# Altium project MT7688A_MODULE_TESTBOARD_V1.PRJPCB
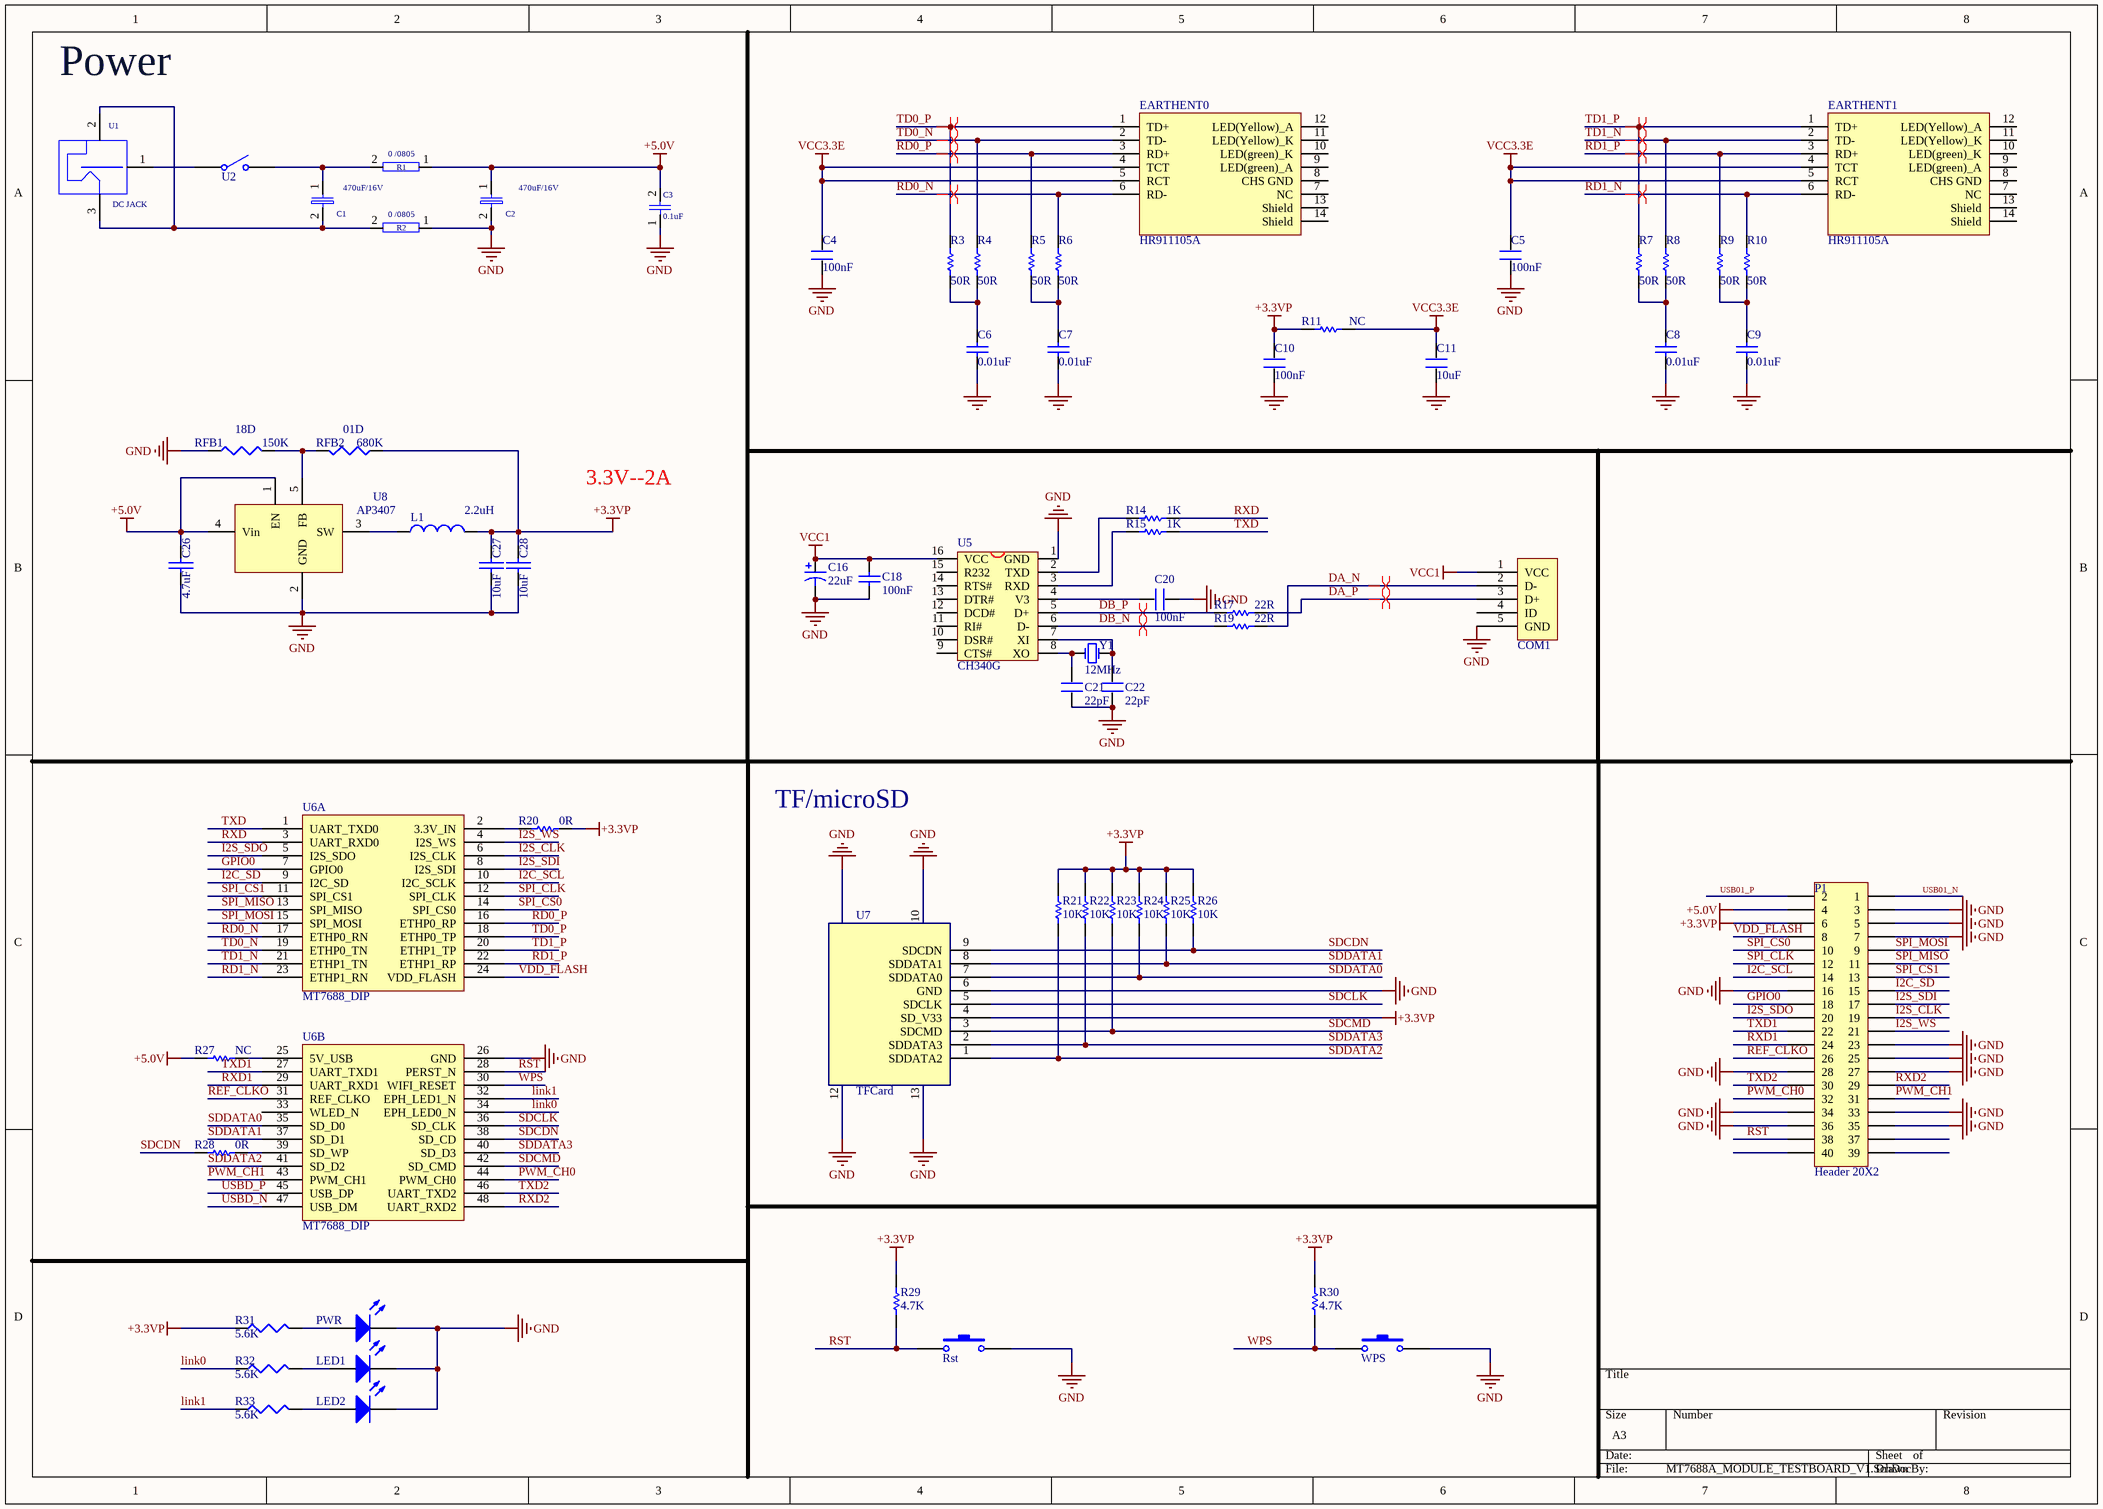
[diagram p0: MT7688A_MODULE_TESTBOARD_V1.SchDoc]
3 sheets, 120 parts. Net scope: global (net labels, ports and power ports of the same name join across sheets).
Sheets:
  MT7688A_MODULE_TESTBOARD_V1.SchDoc
  wm8960.SchDoc
  GL850G.SchDoc

## Sheet MT7688A_MODULE_TESTBOARD_V1.SchDoc
size A3

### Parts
C1  value 470uF/16V  [DL3 SMT470uF]  (hidden comment: E_CAP/3580)
C2  value 470uF/16V  [DL3 SMT470uF]  (hidden comment: E_CAP/3580)
C3  value 0.1uF  [RLC 0402 M35]  (hidden comment: CAP/0402)
C4  100nF  [RLC 0402 M35]
C5  100nF  [RLC 0402 M35]
C6  value 0.01uF  [RLC 0402 M35]  (hidden comment: Cap Semi)
C7  value 0.01uF  [RLC 0402 M35]  (hidden comment: Cap Semi)
C8  value 0.01uF  [RLC 0402 M35]  (hidden comment: Cap Semi)
C9  value 0.01uF  [RLC 0402 M35]  (hidden comment: Cap Semi)
C10  100nF  [RLC 0402 M35]
C11  10uF  [RLC 0402 M35]
C16  22uF  [C1206L]
C18  value 100nF  [RLC 0402 M35]  (hidden comment: Cap Semi)
C20  100nF  [RLC 0402 M35]
C21  22pF  [RLC 0402 M35]
C22  22pF  [RLC 0402 M35]
C26  4.7uF  [RLC 0402 M35]
C27  10uF  [RLC 0402 M35]
C28  10uF  [RLC 0402 M35]
COM1  USB mini-b  [USB mini-B]  (value not drawn)
EARTHENT0  HR911105A  [HR911105A]
EARTHENT1  HR911105A  [HR911105A]
L1  2.2uH  [L5.5x5.5]
LED1  leds_0603  [leds_0603]  (value not drawn)
LED2  leds_0603  [leds_0603]  (value not drawn)
P1  Header 20X2  [HDR2X20]
PWR  leds_0603  [leds_0603]  (value not drawn)
R1  value 0 /0805  [0805]  (hidden comment: RES/0805)
R2  value 0 /0805  [0805]  (hidden comment: RES/0805)
R3  value 50R  [RLC 0402 M35]  (hidden comment: Res Semi)
R4  value 50R  [RLC 0402 M35]  (hidden comment: Res Semi)
R5  value 50R  [RLC 0402 M35]  (hidden comment: Res Semi)
R6  value 50R  [RLC 0402 M35]  (hidden comment: Res Semi)
R7  value 50R  [RLC 0402 M35]  (hidden comment: Res Semi)
R8  value 50R  [RLC 0402 M35]  (hidden comment: Res Semi)
R9  value 50R  [RLC 0402 M35]  (hidden comment: Res Semi)
R10  value 50R  [RLC 0402 M35]  (hidden comment: Res Semi)
R11  value NC  [R0603]  (hidden comment: Res Semi)
R14  value 1K  [RLC 0402 M35]  (hidden comment: Res Semi)
R15  value 1K  [RLC 0402 M35]  (hidden comment: Res Semi)
R17  value 22R  [RLC 0402 M35]  (hidden comment: Res Semi)
R19  value 22R  [RLC 0402 M35]  (hidden comment: Res Semi)
R20  value 0R  [RLC 0402 M35]  (hidden comment: Res Semi)
R21  value 10K  [RLC 0402 M35]  (hidden comment: Res Semi)
R22  value 10K  [RLC 0402 M35]  (hidden comment: Res Semi)
R23  value 10K  [RLC 0402 M35]  (hidden comment: Res Semi)
R24  value 10K  [RLC 0402 M35]  (hidden comment: Res Semi)
R25  value 10K  [RLC 0402 M35]  (hidden comment: Res Semi)
R26  value 10K  [RLC 0402 M35]  (hidden comment: Res Semi)
R27  value NC  [RLC 0402 M35]  (hidden comment: Res Semi)
R28  value 0R  [RLC 0402 M35]  (hidden comment: Res Semi)
R29  value 4.7K  [RLC 0402 M35]  (hidden comment: Res Semi)
R30  value 4.7K  [RLC 0402 M35]  (hidden comment: Res Semi)
R31  value 5.6K  [RLC 0402 M35]  (hidden comment: Res3)
R32  value 5.6K  [RLC 0402 M35]  (hidden comment: Res3)
R33  value 5.6K  [RLC 0402 M35]  (hidden comment: Res3)
RFB1  150K  [RLC 0402 M35]
RFB2  680K  [RLC 0402 M35]
Rst  key  [2x4SWD]  (value not drawn)
U1  value DC JACK  [DC011C]  (hidden comment: DC_JACK)
U2  switch_on_off  [switch_bodong_90]  (value not drawn)
U5  CH340G  [SO-16]
U6  MT7688_DIP  [MT7688_DIP]  (parts A,B of 2)
U7  TFCard  [TFCard]
U8  AP3407  [SOT23-5L]
WPS  key  [2x4SWD]  (value not drawn)
Y1  12MHz  [XTAL-DIP2S94]

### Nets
+3.3VP: C10.2 C27.1 C28.1 L1.2 P1.6 R11.2 R20.1 R21.2 R22.2 R23.2 R24.2 R25.2 R26.2 R29.2 R30.2 R31.1 RFB2.1 U7.4(SD_V33)
+5.0V: C2.1 C3.2 C26.1 P1.4 R1.1 R27.2 U8.1(EN) U8.4(Vin)
GND: C2.2 C3.1 C4.1 C5.1 C6.2 C7.2 C8.2 C9.2 C10.1 C11.1 C16.2 C18.2 C20.1 C21.1 C22.1 C26.2 C27.2 C28.2 COM1.5(GND) LED1.2(K) LED2.2(K) P1.3 P1.5 P1.7 P1.16 P1.23 P1.25 P1.27 P1.28 P1.33 P1.34 P1.35 P1.36 PWR.2(K) R2.1 RFB1.1 Rst.1 U5.1(GND) U6.26(GND) U7.6(GND) U7.10 U7.12 U7.13 U7.?1 U8.2(GND) WPS.1
VCC1: C16.1 C18.1 COM1.1(VCC) U5.16(VCC)
VCC3.3E: C4.2 C5.2 C11.2 EARTHENT0.4(TCT) EARTHENT0.5(RCT) EARTHENT1.4(TCT) EARTHENT1.5(RCT) R11.1
DA_N: COM1.2(D-) R19.2
DA_P: COM1.3(D+) R17.2
DB_N: R19.1 U5.6(D-)
DB_P: R17.1 U5.5(D+)
GPIO0: P1.18 U6.7(GPIO0)
I2C_SCL: P1.14 U6.10(I2C_SCLK)
I2C_SD: P1.15 U6.9(I2C_SD)
I2S_CLK: P1.19 U6.6(I2S_CLK)
I2S_SDI: P1.17 U6.8(I2S_SDI)
I2S_SDO: P1.20 U6.5(I2S_SDO)
I2S_WS: P1.21 U6.4(I2S_WS)
link0: R32.1 U6.34(EPH_LED0_N)
link1: R33.1 U6.32(EPH_LED1_N)
PWM_CH0: P1.32 U6.44(PWM_CH0)
PWM_CH1: P1.31 U6.43(PWM_CH1)
RD0_N: EARTHENT0.6(RD-) R6.2 U6.17(ETHP0_RN)
RD0_P: EARTHENT0.3(RD+) R5.2 U6.16(ETHP0_RP)
RD1_N: EARTHENT1.6(RD-) R10.2 U6.23(ETHP1_RN)
RD1_P: EARTHENT1.3(RD+) R9.2 U6.22(ETHP1_RP)
REF_CLKO: P1.26 U6.31(REF_CLKO)
RST: P1.38 R29.1 Rst.2 U6.28(PERST_N)
RXD: R14.2 U6.3(UART_RXD0)
RXD1: P1.24 U6.29(UART_RXD1)
RXD2: P1.29 U6.48(UART_RXD2)
SDCDN: R26.1 R28.2 U6.38(SD_CD) U7.9(SDCDN)
SDCLK: U6.36(SD_CLK) U7.5(SDCLK)
SDCMD: R23.1 U6.42(SD_CMD) U7.3(SDCMD)
SDDATA0: R24.1 U6.35(SD_D0) U7.7(SDDATA0)
SDDATA1: R25.1 U6.37(SD_D1) U7.8(SDDATA1)
SDDATA2: R21.1 U6.41(SD_D2) U7.1(SDDATA2)
SDDATA3: R22.1 U6.40(SD_D3) U7.2(SDDATA3)
SPI_CLK: P1.12 U6.12(SPI_CLK)
SPI_CS0: P1.10 U6.14(SPI_CS0)
SPI_CS1: P1.13 U6.11(SPI_CS1)
SPI_MISO: P1.11 U6.13(SPI_MISO)
SPI_MOSI: P1.9 U6.15(SPI_MOSI)
TD0_N: EARTHENT0.2(TD-) R4.2 U6.19(ETHP0_TN)
TD0_P: EARTHENT0.1(TD+) R3.2 U6.18(ETHP0_TP)
TD1_N: EARTHENT1.2(TD-) R8.2 U6.21(ETHP1_TN)
TD1_P: EARTHENT1.1(TD+) R7.2 U6.20(ETHP1_TP)
TXD: R15.2 U6.1(UART_TXD0)
TXD1: P1.22 U6.27(UART_TXD1)
TXD2: P1.30 U6.46(UART_TXD2)
USB01_N: P1.1
USB01_P: P1.2
USBD_N: U6.47(USB_DM)
USBD_P: U6.45(USB_DP)
VDD_FLASH: P1.8 U6.24(VDD_FLASH)
WPS: R30.1 U6.30(WIFI_RESET) WPS.2
NetC1_1: C1.1 R1.2 U2.2(NO)
NetC1_2: C1.2 R2.2 U1.2 U1.3
NetC6_1: C6.1 R3.1 R4.1
NetC7_1: C7.1 R5.1 R6.1
NetC8_1: C8.1 R7.1 R8.1
NetC9_1: C9.1 R9.1 R10.1
NetC20_2: C20.2 U5.4(V3)
NetC21_2: C21.2 U5.8(XO) Y1.2(OSC2)
NetC22_2: C22.2 U5.7(XI) Y1.1(OSC1)
NetL1_1: L1.1 U8.3(SW)
NetLED1_1: LED1.1(A) R32.2
NetLED2_1: LED2.1(A) R33.2
NetPWR_1: PWR.1(A) R31.2
NetR14_1: R14.1 U5.2(TXD)
NetR15_1: R15.1 U5.3(RXD)
NetR20_2: R20.2 U6.2(3.3V_IN)
NetR27_1: R27.1 U6.25(5V_USB)
NetR28_1: R28.1 U6.39(SD_WP)
NetRFB1_2: RFB1.2 RFB2.2 U8.5(FB)
NetU1_1: U1.1 U2.1(COMMON)

Not connected (* = marked no-connect by the designer): COM1 4(ID); EARTHENT0 7(NC) 8(CHS_GND) 9(LED(green)_A) 10(LED(green)_K) 11(LED(Yellow)_K) 12(LED(Yellow)_A) 13(Shield) 14(Shield); EARTHENT1 7(NC) 8(CHS_GND) 9(LED(green)_A) 10(LED(green)_K) 11(LED(Yellow)_K) 12(LED(Yellow)_A) 13(Shield) 14(Shield); P1 37 39 40; U5 9(CTS#) 10(DSR#) 11(RI#) 12(DCD#) 13(DTR#) 14(RTS#) 15(R232); U6 33(WLED_N)

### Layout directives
differential pair: DA_N, DA_P, DB_N, DB_P, RD0_N, RD0_P, RD1_N, RD1_P, TD0_N, TD0_P, TD1_N, TD1_P

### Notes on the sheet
- Power
- (near RFB1) 18D
- (near RFB2) 01D
- 3.3V--2A
- TF/microSD

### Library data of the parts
C1 C2 = E_CAP/3580: PCB DECAL: CAP-3580-DIP
C3 = CAP/0402: Geometry.Height: 0.5mm; PCB DECAL: 0402
C4 C5 C10 C11 C20-C22 = C
C6-C9 C18 = Cap Semi: Capacitor (Semiconductor SIM Model)
C16 = cap_t
C26-C28 = CAP 2M: Capacitor 0.2 pitch
EARTHENT0 EARTHENT1 = HR911105A: Pb-free,接线端子,KF102-3.81-2,2引脚,间距:3.81mm,绿色,额定电压:300V,电流10A,接触电阻：20mΩ,绝缘电阻 5000Ω/1000V,耐压:AC1500V\1min,-40~105℃; Part Number: 3DZ0105115
L1 = Inductor: Code_IEC: 1005; Value: 10mH
P1 = Header 20X2: Header, 20-Pin, Dual row
R1 R2 = RES/0805: Geometry.Height: 0.5mm
R3-R11 R14 R15 R17 R19-R30 = Res Semi: Semiconductor Resistor
R31-R33 = Res3: Resistor
RFB1 RFB2 = RES1
U1 = DC_JACK: PCB DECAL: DC-JACK-V-DIP
U5 = CH340G: USB2UART
Y1 = XTAL_2: Crystal Oscillator

## Sheet wm8960.SchDoc
size A3
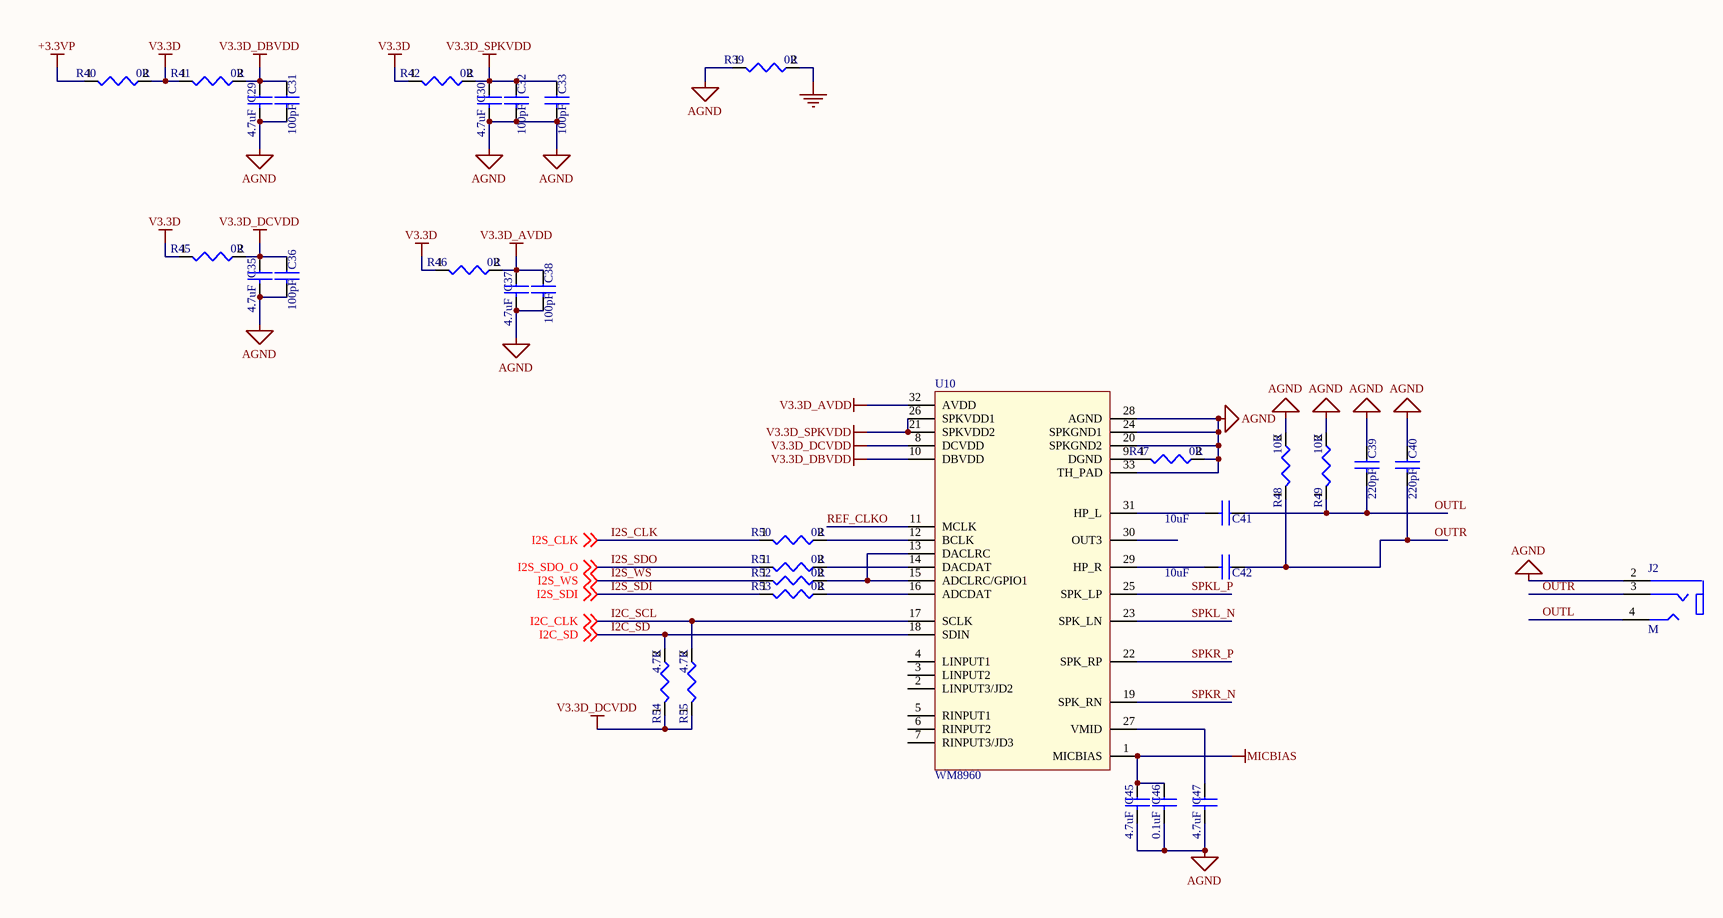
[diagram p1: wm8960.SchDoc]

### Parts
C29  4.7uF  [RLC 0402 M35]
C30  4.7uF  [RLC 0402 M35]
C31  100pF  [RLC 0402 M35]
C32  100pF  [RLC 0402 M35]
C33  100pF  [RLC 0402 M35]
C35  4.7uF  [RLC 0402 M35]
C36  100pF  [RLC 0402 M35]
C37  4.7uF  [RLC 0402 M35]
C38  100pF  [RLC 0402 M35]
C39  220pF  [RLC 0402 M35]
C40  220pF  [RLC 0402 M35]
C41  10uF  [C0603]
C42  10uF  [C0603]
C45  4.7uF  [RLC 0402 M35]
C46  0.1uF  [RLC 0402 M35]
C47  4.7uF  [RLC 0402 M35]
J2  M  [PJ-313]
R39  0R  [RLC 0402 M35]
R40  0R  [R0603]
R41  0R  [RLC 0402 M35]
R42  0R  [RLC 0402 M35]
R45  0R  [RLC 0402 M35]
R46  0R  [RLC 0402 M35]
R47  0R  [RLC 0402 M35]
R48  10K  [RLC 0402 M35]
R49  10K  [RLC 0402 M35]
R50  0R  [RLC 0402 M35]
R51  0R  [RLC 0402 M35]
R52  0R  [RLC 0402 M35]
R53  0R  [RLC 0402 M35]
R54  4.7K  [RLC 0402 M35]
R55  4.7K  [RLC 0402 M35]
U10  WM8960  [QFN_32]

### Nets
+3.3VP: R40.1
AGND: C29.2 C30.2 C31.2 C32.2 C33.2 C35.2 C36.2 C37.2 C38.2 C39.1 C40.1 C45.2 C46.2 C47.2 J2.2 R39.1 R47.2 R48.2 R49.2 U10.20(SPKGND2) U10.24(SPKGND1) U10.28(AGND) U10.33(TH_PAD)
GND: R39.2
MICBIAS: C45.1 C46.1 U10.1(MICBIAS)
V3.3D: R40.2 R41.1 R42.1 R45.1 R46.1
V3.3D_AVDD: C37.1 C38.1 R46.2 U10.32(AVDD)
V3.3D_DBVDD: C29.1 C31.1 R41.2 U10.10(DBVDD)
V3.3D_DCVDD: C35.1 C36.1 R45.2 R54.1 R55.1 U10.8(DCVDD)
V3.3D_SPKVDD: C30.1 C32.1 C33.1 R42.2 U10.21(SPKVDD2) U10.26(SPKVDD1)
I2C_SCL: R55.2 U10.17(SCLK) ; off-sheet I2C_CLK  [also labelled I2C_CLK]
I2C_SD: R54.2 U10.18(SDIN) ; off-sheet I2C_SD
I2S_CLK: R50.1 ; off-sheet I2S_CLK
I2S_SDI: R53.1 ; off-sheet I2S_SDI
I2S_SDO: R51.1 ; off-sheet I2S_SDO_O  [also labelled I2S_SDO_O]
I2S_WS: R52.1 ; off-sheet I2S_WS
OUTL: C39.2 C41.1 J2.4 R49.1
OUTR: C40.2 C42.1 J2.3 R48.1
REF_CLKO: U10.11(MCLK)
SPKL_N: U10.23(SPK_LN)
SPKL_P: U10.25(SPK_LP)
SPKR_N: U10.19(SPK_RN)
SPKR_P: U10.22(SPK_RP)
NetC41_2: C41.2 U10.31(HP_L)
NetC42_2: C42.2 U10.29(HP_R)
NetC47_1: C47.1 U10.27(VMID)
NetR47_1: R47.1 U10.9(DGND)
NetR50_2: R50.2 U10.12(BCLK)
NetR51_2: R51.2 U10.14(DACDAT)
NetR52_2: R52.2 U10.13(DACLRC) U10.15(ADCLRC/GPIO1)
NetR53_2: R53.2 U10.16(ADCDAT)

Not connected (* = marked no-connect by the designer): U10 2(LINPUT3/JD2) 3(LINPUT2) 4(LINPUT1) 5(RINPUT1) 6(RINPUT2) 7(RINPUT3/JD3) 30(OUT3)

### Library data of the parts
C29-C33 C35-C42 C45-C47 = CAP NP
J2 = Component_1
R39-R42 R45-R55 = RES/0402_3

## Sheet GL850G.SchDoc
size A4
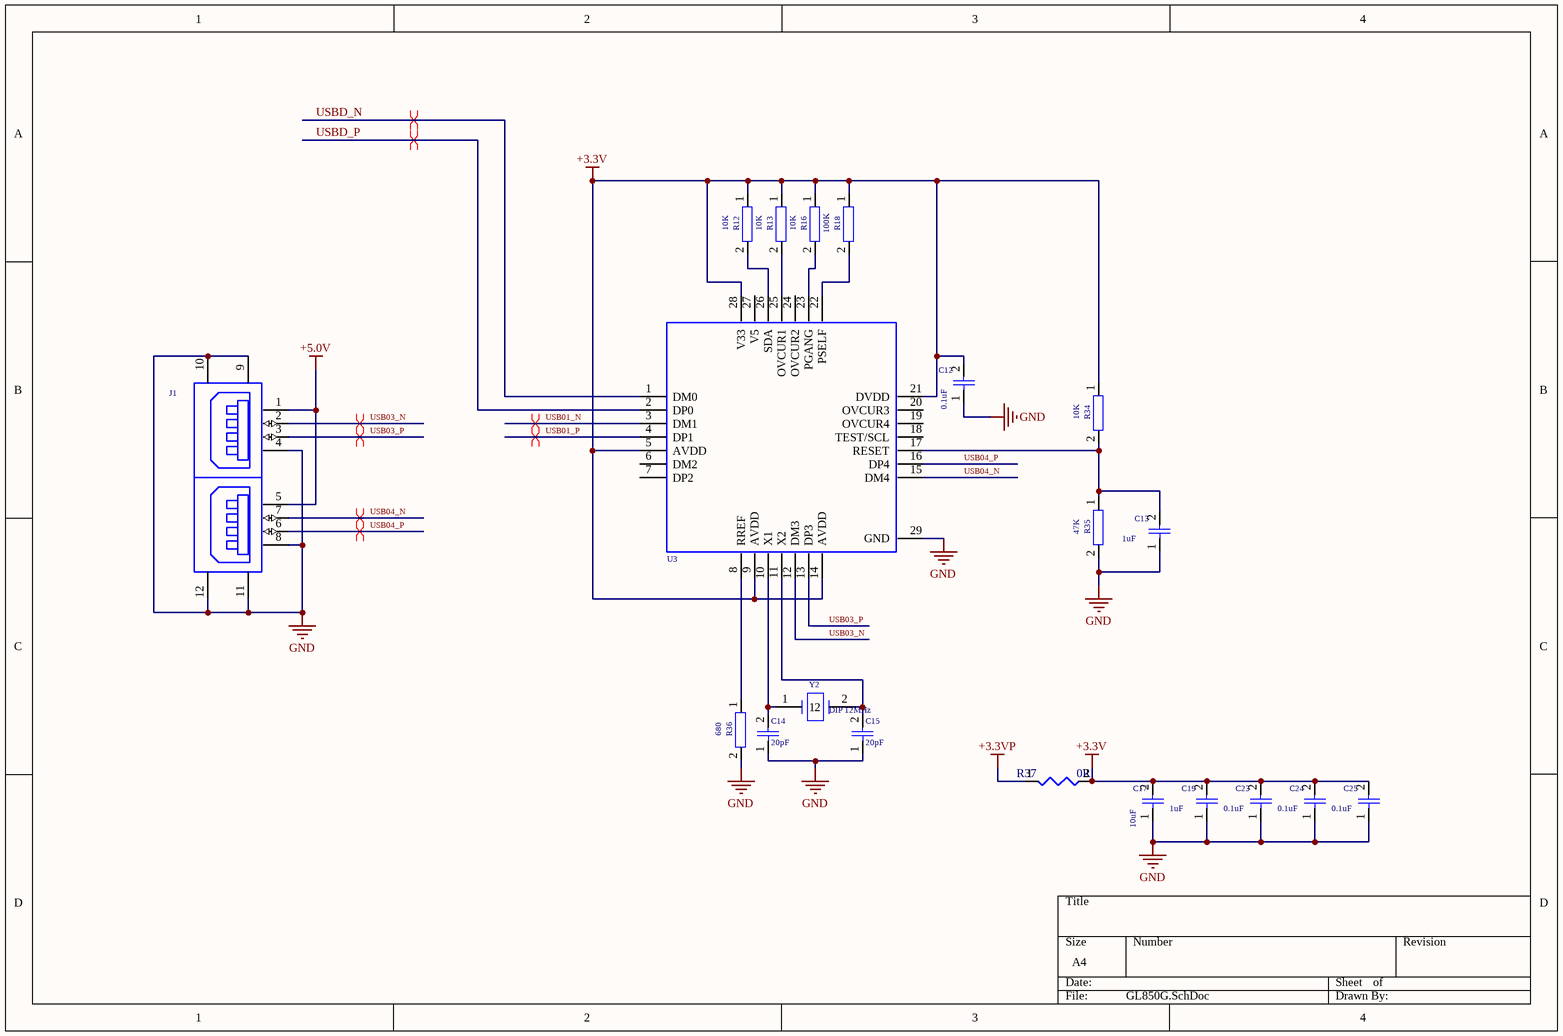
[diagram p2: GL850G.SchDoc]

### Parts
C12  value 0.1uF  [RLC 0402 M35]  (hidden comment: CAP/0603)
C13  value 1uF  [RLC 0402 M35]  (hidden comment: CAP/0603)
C14  value 20pF  [RLC 0402 M35]  (hidden comment: CAP/0402)
C15  value 20pF  [RLC 0402 M35]  (hidden comment: CAP/0402)
C17  value 10uF  [RLC 0402 M35]  (hidden comment: CAP/0603)
C19  value 1uF  [RLC 0402 M35]  (hidden comment: CAP/0603)
C23  value 0.1uF  [RLC 0402 M35]  (hidden comment: CAP/0603)
C24  value 0.1uF  [RLC 0402 M35]  (hidden comment: CAP/0603)
C25  value 0.1uF  [RLC 0402 M35]  (hidden comment: CAP/0603)
J1  USB_A-H  [USB-DB]  (value not drawn)
R12  value 10K  [RLC 0402 M35]  (hidden comment: RES/0402)
R13  value 10K  [RLC 0402 M35]  (hidden comment: RES/0402)
R16  value 10K  [RLC 0402 M35]  (hidden comment: RES/0402)
R18  value 100K  [RLC 0402 M35]  (hidden comment: RES/0402)
R34  value 10K  [RLC 0402 M35]  (hidden comment: RES/0402)
R35  value 47K  [RLC 0402 M35]  (hidden comment: RES/0402)
R36  value 680  [RLC 0402 M35]  (hidden comment: RES/0402)
R37  0R  [R0603]
U3  GL580G-QFN28  [GL850G-31]  (value not drawn)
Y2  value DIP 12MHz  [XTAL-DIP2S94]  (hidden comment: CRYSTAL-3X9_0)

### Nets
+3.3V: C12.2 C17.2 C19.2 C23.2 C24.2 C25.2 R12.1 R13.1 R16.1 R18.1 R34.1 R37.2 U3.5(AVDD) U3.9(AVDD) U3.14(AVDD) U3.21(DVDD) U3.28(V33)
+3.3VP: R37.1
+5.0V: J1.1(V+) J1.5(NC)
GND: C12.1 C13.1 C14.1 C15.1 C17.1 C19.1 C23.1 C24.1 C25.1 J1.4(G) J1.8(NC) J1.9 J1.10 J1.11 J1.12 R35.2 R36.2 U3.29(GND)
USB01_N: U3.3(DM1)
USB01_P: U3.4(DP1)
USB03_N: J1.2(D-) U3.12(DM3)
USB03_P: J1.3(D+) U3.13(DP3)
USB04_N: J1.7(NC) U3.15(DM4)
USB04_P: J1.6(NC) U3.16(DP4)
USBD_N: U3.1(DM0)
USBD_P: U3.2(DP0)
NetC13_2: C13.2 R34.2 R35.1 U3.17(RESET)
NetC14_2: C14.2 U3.10(X1) Y2.1
NetC15_2: C15.2 U3.11(X2) Y2.2
NetR12_2: R12.2 U3.26(SDA)
NetR13_2: R13.2 U3.25(OVCUR1)
NetR16_2: R16.2 U3.23(PGANG)
NetR18_2: R18.2 U3.22(PSELF)
NetR36_1: R36.1 U3.8(RREF)

Not connected (* = marked no-connect by the designer): U3 6(DM2) 7(DP2) 18(TEST/SCL) 19(OVCUR4) 20(OVCUR3) 24(OVCUR2) 27(V5)

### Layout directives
differential pair: USB01_N, USB01_P, USB03_N, USB03_P, USB04_N, USB04_P, USBD_N, USBD_P

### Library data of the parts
C12 C13 C17 C19 C23-C25 = CAP/0603: PCB DECAL: 0603
C14 C15 = CAP/0402: Geometry.Height: 0.5mm; PCB DECAL: 0402
J1 = USB_A-H: PCB DECAL: USB/4P/P2.0/DIP/R/F/SUA-110VB-B2N
R12 R13 R16 R18 R34-R36 = RES/0402: Geometry.Height: 0.5mm; PCB DECAL: 0402
R37 = RES/0402_3
U3 = GL580G-QFN28: Value: GL580G-31
Y2 = CRYSTAL-3X9_0: Source_Path: D:\PROJECT\RT6856\SCH\AP-RT6856-RT5592EP-V10-SG-SPI-CONSURRENT-DDRI-GPHY-110823.DSN; PCB DECAL: CRYS/DIP/D5X10.6/GB2000025/ECERA

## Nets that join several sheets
+3.3VP: MT7688A_MODULE_TESTBOARD_V1 (18 pins), wm8960 (R40.1), GL850G (R37.1)
+5.0V: MT7688A_MODULE_TESTBOARD_V1 (8 pins), GL850G (J1.1 J1.5)
GND: MT7688A_MODULE_TESTBOARD_V1 (46 pins), wm8960 (R39.2), GL850G (18 pins)
I2C_SCL: MT7688A_MODULE_TESTBOARD_V1 (P1.14 U6.10), wm8960 (R55.2 U10.17)
I2C_SD: MT7688A_MODULE_TESTBOARD_V1 (P1.15 U6.9), wm8960 (R54.2 U10.18)
I2S_CLK: MT7688A_MODULE_TESTBOARD_V1 (P1.19 U6.6), wm8960 (R50.1)
I2S_SDI: MT7688A_MODULE_TESTBOARD_V1 (P1.17 U6.8), wm8960 (R53.1)
I2S_SDO: MT7688A_MODULE_TESTBOARD_V1 (P1.20 U6.5), wm8960 (R51.1)
I2S_WS: MT7688A_MODULE_TESTBOARD_V1 (P1.21 U6.4), wm8960 (R52.1)
REF_CLKO: MT7688A_MODULE_TESTBOARD_V1 (P1.26 U6.31), wm8960 (U10.11)
USB01_N: MT7688A_MODULE_TESTBOARD_V1 (P1.1), GL850G (U3.3)
USB01_P: MT7688A_MODULE_TESTBOARD_V1 (P1.2), GL850G (U3.4)
USBD_N: MT7688A_MODULE_TESTBOARD_V1 (U6.47), GL850G (U3.1)
USBD_P: MT7688A_MODULE_TESTBOARD_V1 (U6.45), GL850G (U3.2)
